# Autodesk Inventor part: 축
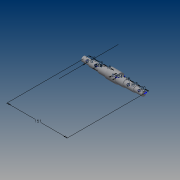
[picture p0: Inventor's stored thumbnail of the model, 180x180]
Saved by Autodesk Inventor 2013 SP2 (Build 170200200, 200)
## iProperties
Created: 2014-12
Part Number: 축
Material: Generic
Document SubType Name: Modeling
Designer: CADB206
Density: 1 g/cm^3
Author: CADB206
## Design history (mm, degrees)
sketch "스케치1"
  geometry: L1 (-75.5, 0)-(75.5, 0); L2 (-75.5, 0)-(-75.5, 6); L3 (-75.5, 6)-(-55.5, 6); L4 (-55.5, 6)-(-55.5, 7.5); L5 (-55.5, 7.5)-(-30.5, 7.5); L6 (-30.5, 7.5)-(-30.5, 9); L7 (-30.5, 9)-(30.5, 9); L8 (30.5, 9)-(30.5, 7.5); L9 (30.5, 7.5)-(55.5, 7.5); L10 (55.5, 7.5)-(55.5, 6); L11 (55.5, 6)-(75.5, 6); L12 (75.5, 6)-(75.5, 0); L13 (-12.5, 14)-(12.5, 14); L14 (12.5, 14)-(12.5, 2); L15 (12.5, 2)-(-12.5, 2); L16 (-12.5, 2)-(-12.5, 14); 2 further points
  constraints: 32 end point, 10 parallel, 3 perpendicular, 2 horizontal, 1 coincident, 1 collinear, 1 midpoint
  dimensions: "d0" = 151 distance of L1.start L1.end; "d1" = 12 diameter of L3 L1; "d2" = 15 diameter of L5 L1; "d3" = 18 diameter of L7 L1; "d4" = 2 distance between parallel lines of L1 L15; "d5" = 24 diameter of L13 L15; "d6" = 20 distance between parallel lines of L4 L2; "d7" = 25 distance between parallel lines of L6 L4; "d8" = 18 distance between parallel lines of L16 L6; "d9" = 18 distance between parallel lines of L8 L14; "d10" = 15 diameter of L9 L1; "d11" = 12 diameter of L11 L1; "d12" = 25 distance between parallel lines of L10 L8; "d13" = 20 distance between parallel lines of L12 L10
revolve "회전1" stored, may be unused: angle "d14" = 90 deg
revolve "회전2" stored, may be unused: angle "d15" = 90 deg
node "작업 평면1"
sketch "스케치2"
  geometry: L1 (-10, 6)-(-10, -6) reference; L2 (10, 6)-(10, -6) reference; L3 (10, 6)-(-10, 6) reference; L4 (10, -6)-(-10, -6) reference; L5 (-1.5, 2.5)-(10, 2.5); L6 (10, 2.5)-(10, -2.5); L7 (10, -2.5)-(-1.5, -2.5); L8 (-4, 0)-(-4, 0); A1 r 2.5 centre (-1.5, 0) between (-1.5, 2.5) and (-4, 0); A2 r 2.5 centre (-1.5, 0) between (-4, 0) and (-1.5, -2.5); 2 further points
  constraints: 8 end point, 4 point on circle, 4 tangent, 2 centre point, 2 parallel, 1 concentric, 1 horizontal, 1 horizontal alignment, 1 midpoint, 1 perpendicular, 1 point on line
  dimensions: "d16" = 14 distance between parallel lines of L6 L8; "d18" = 5 distance between parallel lines of L5 L7; "d19" = 2.5 radius of A1
extrude "돌출1" cut sketch "스케치2" distance "d20" = 3; taper "d21" = 0 deg
node "솔리드1"
mirror "대칭1"
node "투영된 루프1"
